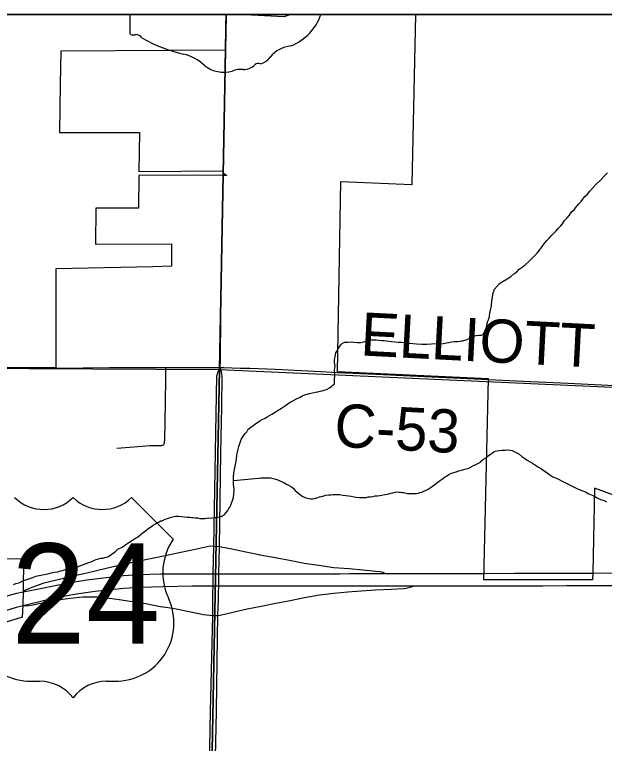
# Model space of a CAD drawing. Extents: x 0 to 34, y 0 to 22.
# Drawn here: x 6.216 to 6.991, y 19.941 to 20.9 of the extents above; entities that cross this region are included whole.
import ezdxf

# ---------------------------------------------------------------- set-up
doc = ezdxf.new("R2010")
doc.units = 0
for name, color, linetype in [('Default', 7, 'Continuous'), ('GM_X_City_Street', 7, 'Continuous'), ('GM_X_County_Road', 7, 'Continuous'), ('GM_X_County_Road_Text', 7, 'Continuous'), ('GM_X_Interchange_Ramps', 7, 'Continuous'), ('GM_X_Minor_River', 7, 'Continuous'), ('GM_X_Section', 7, 'Continuous'), ('GM_X_State_Route', 7, 'Continuous'), ('GM_X_Township_Road', 7, 'Continuous'), ('GM_X_Unincorporated_Text', 7, 'Continuous'), ('GM_X_US_Location', 7, 'Continuous'), ('GM_X_US_Route', 7, 'Continuous'), ('GM_X_US_Shield', 7, 'Continuous'), ('SH_Data', 7, 'Continuous')]:
    doc.layers.add(name, color=color, linetype=linetype)

msp = doc.modelspace()

# ---------------------------------------------------------------- linework, layer by layer
at = {"layer": 'Default'}
for points in [[(6.49402, 20.9), (5.49304, 20.9), (5.48293, 20.43816), (6.48534, 20.43303)], [(7.49088, 20.9), (6.49402, 20.9), (6.48534, 20.43303), (7.47924, 20.38842)]]:
    msp.add_lwpolyline(points, close=True, dxfattribs=at)
for points in [[(7.05728, 20.24803), (6.97837, 20.27716), (6.97611, 20.16577), (6.97572, 20.15654), (6.83292, 20.15618), (6.8388, 20.42065), (6.64029, 20.42983), (6.64454, 20.6803), (6.73852, 20.67644), (6.74355, 20.9), (6.5785, 20.9), (6.57014, 20.89705), (6.51038, 20.9), (6.49373, 20.9), (6.4929, 20.85332), (6.27639, 20.85193), (6.27568, 20.80908), (6.27458, 20.74489), (6.38016, 20.74486), (6.37927, 20.6937), (6.4902, 20.69438), (6.49015, 20.69161), (6.49485, 20.68811), (6.4901, 20.68847), (6.45677, 20.68866), (6.37919, 20.68816), (6.37847, 20.64553), (6.32271, 20.64518), (6.32199, 20.59781), (6.42221, 20.59822), (6.42195, 20.56879), (6.39789, 20.56827), (6.27007, 20.56534), (6.26978, 20.43556), (6.18963, 20.43507)], [(6.13367, 20.18377), (6.22753, 20.18449), (6.22689, 20.14091), (6.22664, 20.12302), (6.22582, 20.10729), (6.1749, 20.09133)]]:
    msp.add_lwpolyline(points, dxfattribs=at)
at = {"layer": 'GM_X_City_Street'}
for points in [[(6.41208, 20.33454), (6.41243, 20.33543), (6.41268, 20.33633), (6.41287, 20.33746), (6.41307, 20.33859), (6.41311, 20.33976), (6.41363, 20.3646), (6.41403, 20.3907), (6.41444, 20.4205), (6.41465, 20.43559)], [(6.35021, 20.32963), (6.35582, 20.33001), (6.3776, 20.3318), (6.39379, 20.33295), (6.40814, 20.33328), (6.40903, 20.33326), (6.40991, 20.33336), (6.4108, 20.3336), (6.41149, 20.33395), (6.41208, 20.33454)]]:
    msp.add_lwpolyline(points, dxfattribs=at)
at = {"layer": 'GM_X_County_Road'}
for points in [[(6.14024, 20.43373), (6.18986, 20.43451), (6.27002, 20.43501), (6.27101, 20.43502)], [(6.27101, 20.43502), (6.34054, 20.43578), (6.39955, 20.43561), (6.41465, 20.43559)], [(6.41465, 20.43559), (6.45455, 20.43556), (6.4862, 20.43568)], [(6.4862, 20.43568), (6.49126, 20.43554), (6.51238, 20.43497), (6.52488, 20.43471), (6.55848, 20.43347), (6.61851, 20.43033), (6.64052, 20.42928)], [(6.64052, 20.42928), (6.67097, 20.42784), (6.70995, 20.42613), (6.71737, 20.42577), (6.79271, 20.42206), (6.83903, 20.4201)], [(6.83903, 20.4201), (6.88486, 20.41771), (6.94386, 20.41488), (7.0395, 20.41007), (7.04664, 20.40978)]]:
    msp.add_lwpolyline(points, dxfattribs=at)
at = {"layer": 'GM_X_Interchange_Ramps'}
msp.add_line((6.47621, 20.10924), (6.48318, 20.10936), dxfattribs=at)
for points in [[(6.48502, 20.19975), (6.47767, 20.20037), (6.4727, 20.20055), (6.4534, 20.19639), (6.43432, 20.19244), (6.41611, 20.18849), (6.39681, 20.18432), (6.37729, 20.18059), (6.35887, 20.17643), (6.33606, 20.17116), (6.32365, 20.16801), (6.30903, 20.16467), (6.29463, 20.16174), (6.27646, 20.15715), (6.25437, 20.1518), (6.23842, 20.14629), (6.23453, 20.14466), (6.23116, 20.14305), (6.22713, 20.14036)], [(6.53752, 20.18914), (6.51986, 20.19288), (6.50121, 20.19661), (6.48748, 20.19921), (6.48502, 20.19975)], [(6.70321, 20.16452), (6.70119, 20.16542), (6.69858, 20.16637), (6.69562, 20.1669), (6.69079, 20.16747), (6.67347, 20.16894), (6.65582, 20.17096), (6.63566, 20.17226), (6.61526, 20.17533), (6.5964, 20.17796), (6.5771, 20.18169), (6.55824, 20.1852), (6.5385, 20.18893), (6.53752, 20.18914)], [(6.48318, 20.10936), (6.48602, 20.11002), (6.50256, 20.11393), (6.52168, 20.11806), (6.54005, 20.12181), (6.55917, 20.12556), (6.57829, 20.12931), (6.59703, 20.13305), (6.61653, 20.13643), (6.63565, 20.13868), (6.65373, 20.14045), (6.67169, 20.14191), (6.69027, 20.14337), (6.71094, 20.144), (6.72731, 20.14495), (6.73086, 20.14543), (6.73409, 20.14609), (6.73765, 20.14706), (6.74098, 20.14856)], [(6.22687, 20.12247), (6.23091, 20.12207), (6.23467, 20.12248), (6.24006, 20.12342), (6.24772, 20.12504), (6.2574, 20.12693), (6.27101, 20.12967), (6.28215, 20.13156), (6.29675, 20.13313), (6.30562, 20.13399), (6.31446, 20.13377), (6.32436, 20.13395), (6.33423, 20.13305), (6.35335, 20.13043), (6.36759, 20.12818), (6.38821, 20.12518), (6.40696, 20.12143), (6.41501, 20.12017)], [(6.41501, 20.12017), (6.42608, 20.11843), (6.4452, 20.11468), (6.46432, 20.11056), (6.47621, 20.10924)]]:
    msp.add_lwpolyline(points, dxfattribs=at)
at = {"layer": 'GM_X_Minor_River'}
for points in [[(6.83907, 20.49841), (6.8395, 20.5003), (6.84032, 20.50218), (6.84037, 20.50408), (6.84083, 20.50672), (6.8413, 20.50975), (6.84177, 20.51278), (6.84221, 20.51466), (6.84265, 20.51693), (6.84273, 20.51959), (6.84316, 20.52148), (6.84322, 20.52338), (6.84367, 20.52564), (6.84411, 20.52791), (6.8446, 20.5317), (6.84505, 20.53396), (6.84588, 20.53622), (6.84671, 20.53886), (6.85339, 20.54627), (6.85803, 20.54917), (6.86344, 20.55243), (6.86809, 20.55534), (6.87237, 20.55902), (6.87625, 20.56157), (6.87939, 20.5649), (6.88327, 20.56783), (6.88754, 20.57112), (6.89145, 20.57481), (6.89535, 20.5785), (6.89928, 20.58256), (6.9028, 20.58626), (6.90595, 20.58998), (6.90872, 20.5937), (6.9115, 20.59779), (6.91583, 20.60299), (6.91896, 20.60632), (6.9221, 20.60965), (6.92485, 20.61261), (6.92797, 20.61556), (6.93072, 20.61852), (6.93346, 20.62148), (6.93622, 20.62483), (6.939, 20.62893), (6.94215, 20.63263), (6.94528, 20.63597), (6.94807, 20.64045), (6.95157, 20.64301), (6.95354, 20.64561), (6.95553, 20.64859), (6.95827, 20.65155), (6.96063, 20.65415), (6.963, 20.65712), (6.96575, 20.66046), (6.96889, 20.66379), (6.97204, 20.6675), (6.97596, 20.67195), (6.98027, 20.67638), (6.98653, 20.68266), (6.99123, 20.68747), (6.99554, 20.6919)], [(6.53309, 20.36206), (6.53503, 20.36352), (6.53813, 20.36533), (6.54122, 20.36714), (6.54507, 20.36893), (6.54778, 20.37076), (6.55087, 20.37257), (6.55397, 20.37438), (6.5586, 20.37691), (6.56247, 20.37945), (6.56674, 20.38237), (6.57331, 20.38636), (6.57681, 20.3893), (6.58068, 20.39147), (6.58724, 20.39508), (6.59109, 20.39687), (6.59494, 20.39866), (6.59878, 20.40007), (6.60338, 20.40146), (6.60759, 20.40248), (6.61141, 20.40313), (6.61446, 20.4038), (6.61752, 20.40447), (6.6202, 20.40515), (6.62288, 20.40584), (6.62479, 20.40616), (6.62672, 20.40724), (6.62981, 20.40906), (6.63254, 20.41126), (6.63448, 20.41272), (6.63641, 20.41381), (6.63653, 20.41798), (6.63662, 20.42102), (6.6367, 20.42368), (6.63658, 20.43242), (6.63703, 20.43507), (6.63747, 20.43696), (6.6368, 20.44002), (6.63647, 20.44192), (6.63655, 20.44458), (6.63704, 20.44837), (6.6371, 20.45027), (6.63755, 20.45253), (6.63837, 20.45479), (6.63997, 20.45741), (6.6412, 20.46041), (6.6424, 20.46266), (6.64477, 20.46563), (6.64673, 20.46785), (6.6498, 20.4689), (6.65399, 20.46916), (6.65817, 20.46942), (6.66196, 20.46893), (6.6665, 20.46842), (6.67107, 20.46867), (6.67642, 20.47004), (6.68102, 20.47142), (6.68484, 20.47207), (6.6875, 20.472), (6.69129, 20.47189), (6.69471, 20.47179), (6.69811, 20.47131), (6.70153, 20.47121), (6.70455, 20.47075), (6.70796, 20.47027), (6.71136, 20.46979), (6.71592, 20.46966), (6.72046, 20.46915), (6.72501, 20.46902), (6.72994, 20.46849), (6.73523, 20.46758), (6.74432, 20.46694), (6.75114, 20.46636), (6.75761, 20.46656), (6.76407, 20.46675), (6.77928, 20.46745), (6.78348, 20.46809), (6.78692, 20.46875), (6.79036, 20.46941), (6.79378, 20.4697), (6.79873, 20.46993), (6.8014, 20.47024), (6.80331, 20.47056), (6.80522, 20.47088), (6.80789, 20.47157), (6.81019, 20.47226), (6.81327, 20.4737), (6.81599, 20.47552), (6.81945, 20.47694), (6.82289, 20.4776), (6.8267, 20.47825), (6.82974, 20.47816), (6.83205, 20.47923), (6.83325, 20.48148), (6.83408, 20.48374), (6.83489, 20.48561), (6.83612, 20.48862), (6.83658, 20.49126), (6.83703, 20.49353), (6.83787, 20.49655), (6.83907, 20.49841)], [(6.29738, 20.17352), (6.29928, 20.17384), (6.3016, 20.17492), (6.30965, 20.17773), (6.31349, 20.17913), (6.31656, 20.18019), (6.31887, 20.18126), (6.3208, 20.18234), (6.3231, 20.18304), (6.32618, 20.18409), (6.32923, 20.18476), (6.3319, 20.18507), (6.33458, 20.18575), (6.33687, 20.18606), (6.33918, 20.18714), (6.34228, 20.18933), (6.34461, 20.19116), (6.3481, 20.19334), (6.35161, 20.19666), (6.35739, 20.19953), (6.36205, 20.20282), (6.36592, 20.20537), (6.36941, 20.20755), (6.37212, 20.20937), (6.37483, 20.21119), (6.37715, 20.21264), (6.37947, 20.2141), (6.38259, 20.21667), (6.38492, 20.2185), (6.38802, 20.22069), (6.39114, 20.22326), (6.39463, 20.22582), (6.39813, 20.22838), (6.40122, 20.23019), (6.40354, 20.23165), (6.40546, 20.23235), (6.40778, 20.2338), (6.40969, 20.23413), (6.41355, 20.2363), (6.41699, 20.23696), (6.4193, 20.23803), (6.4216, 20.23873), (6.42352, 20.23943), (6.42543, 20.23976), (6.42771, 20.24007), (6.42999, 20.24), (6.43189, 20.23995), (6.4425, 20.23888), (6.44439, 20.23883), (6.44629, 20.23877), (6.44818, 20.23834), (6.45045, 20.23827), (6.4531, 20.23782), (6.45614, 20.23773), (6.45954, 20.23725), (6.46296, 20.23715), (6.46599, 20.23707), (6.46828, 20.23738), (6.47019, 20.23771), (6.47285, 20.23763), (6.47551, 20.23793), (6.47856, 20.23822), (6.48199, 20.23851), (6.48505, 20.23918), (6.48733, 20.23949), (6.48966, 20.24095), (6.49199, 20.24278), (6.49356, 20.24463), (6.49631, 20.24759), (6.49752, 20.25022), (6.49872, 20.25209), (6.49994, 20.25471), (6.50115, 20.25734), (6.50239, 20.26072), (6.50365, 20.26486), (6.50418, 20.26979), (6.50426, 20.27283), (6.50433, 20.2751), (6.50404, 20.27815), (6.50378, 20.28234), (6.50354, 20.28691), (6.50368, 20.29184), (6.50421, 20.29677), (6.50511, 20.30168), (6.50561, 20.30585), (6.50651, 20.31038), (6.5074, 20.31492), (6.50795, 20.3206), (6.50882, 20.32438), (6.50969, 20.32815), (6.51056, 20.33193), (6.51386, 20.34095), (6.51586, 20.34431), (6.51746, 20.34693), (6.51903, 20.34878), (6.52099, 20.35101), (6.523, 20.35475), (6.5265, 20.35731), (6.52883, 20.35914), (6.53115, 20.36059), (6.53309, 20.36206)], [(6.81939, 20.30669), (6.82247, 20.30812), (6.82594, 20.30992), (6.82826, 20.31137), (6.83022, 20.31322), (6.83255, 20.31505), (6.83526, 20.31687), (6.83838, 20.31944), (6.84148, 20.32163), (6.84419, 20.32345), (6.84612, 20.32454), (6.84805, 20.32562), (6.85034, 20.32594), (6.85302, 20.32662), (6.85683, 20.32689), (6.86101, 20.32715), (6.86482, 20.32742), (6.86746, 20.32696), (6.87011, 20.32651), (6.87872, 20.32208), (6.88279, 20.31854), (6.88651, 20.31577), (6.88987, 20.31378), (6.89361, 20.31177), (6.89697, 20.30977), (6.90069, 20.30701), (6.90479, 20.30461), (6.90852, 20.30222), (6.91225, 20.29983), (6.9156, 20.29745), (6.9197, 20.29468), (6.92342, 20.29191), (6.92831, 20.29025), (6.93166, 20.28825), (6.93503, 20.28663), (6.93839, 20.28464), (6.94214, 20.28301), (6.94626, 20.28099), (6.95075, 20.27858), (6.956, 20.27615), (6.96164, 20.27409), (6.96651, 20.27204), (6.971, 20.26963), (6.97738, 20.26679), (6.98186, 20.26438), (6.98635, 20.26197), (6.99087, 20.2607), (6.99424, 20.25908)], [(6.50354, 20.28691), (6.53668, 20.29013), (6.53935, 20.29044), (6.54164, 20.29075), (6.54429, 20.29067), (6.54619, 20.29062), (6.54885, 20.29054), (6.55226, 20.29045), (6.55566, 20.28959), (6.55905, 20.28873), (6.56281, 20.28748), (6.56618, 20.28586), (6.56993, 20.28423), (6.57329, 20.28224), (6.57665, 20.28024), (6.58003, 20.27862), (6.58188, 20.27705), (6.58482, 20.27392), (6.58705, 20.27196), (6.58965, 20.26999), (6.59187, 20.26802), (6.5941, 20.26644), (6.59859, 20.26403), (6.60274, 20.26315), (6.60502, 20.26308), (6.60768, 20.26301), (6.60996, 20.26332), (6.61187, 20.26364), (6.61456, 20.26471), (6.61686, 20.2654), (6.61916, 20.26609), (6.62222, 20.26677), (6.62491, 20.26783), (6.6291, 20.26809), (6.63176, 20.26839), (6.63443, 20.2687), (6.63709, 20.26862), (6.64013, 20.26853), (6.64354, 20.26843), (6.64732, 20.26794), (6.65111, 20.26745), (6.65489, 20.26697), (6.6583, 20.26649), (6.66207, 20.26562), (6.6651, 20.26515), (6.66926, 20.26465), (6.67229, 20.26456), (6.67495, 20.26449), (6.678, 20.26478), (6.68068, 20.26546), (6.68373, 20.26576), (6.68677, 20.26605), (6.68983, 20.26672), (6.69288, 20.26701), (6.69593, 20.26731), (6.69859, 20.26761), (6.7028, 20.26863), (6.70547, 20.26893), (6.70777, 20.26962), (6.71045, 20.27031), (6.71313, 20.27099), (6.71619, 20.27166), (6.71847, 20.27198), (6.72113, 20.2719), (6.72303, 20.27184), (6.72529, 20.2714), (6.72719, 20.27134), (6.73058, 20.27048), (6.73247, 20.27005), (6.74006, 20.26983), (6.74234, 20.26977), (6.74463, 20.27008), (6.74692, 20.27039), (6.74884, 20.2711), (6.75114, 20.27179), (6.75382, 20.27286), (6.75691, 20.27429), (6.75961, 20.27573), (6.76232, 20.27755), (6.76542, 20.27974), (6.76815, 20.28194), (6.77086, 20.28377), (6.7759, 20.28742), (6.77824, 20.28925), (6.78096, 20.29145), (6.78366, 20.2929), (6.78676, 20.29509), (6.79022, 20.29651), (6.79329, 20.29756), (6.79636, 20.29861), (6.79981, 20.29965), (6.80326, 20.30069), (6.80632, 20.30137), (6.80939, 20.30242), (6.81284, 20.30346), (6.81592, 20.30489), (6.81939, 20.30669)], [(6.21426, 20.15007), (6.21734, 20.1515), (6.22117, 20.15253), (6.22463, 20.15395), (6.22809, 20.15537), (6.23193, 20.15678), (6.23577, 20.15819), (6.23961, 20.1596), (6.24383, 20.161), (6.24804, 20.16202), (6.25454, 20.16335), (6.2595, 20.16435), (6.2641, 20.16574), (6.2683, 20.16638), (6.2725, 20.16702), (6.27594, 20.16806), (6.27862, 20.16874), (6.2813, 20.16942), (6.28399, 20.17048), (6.28705, 20.17116), (6.29087, 20.17181), (6.29393, 20.17248), (6.29738, 20.17352)]]:
    msp.add_lwpolyline(points, dxfattribs=at)
at = {"layer": 'GM_X_Section'}
for points in [[(5.48293, 20.43816), (6.48534, 20.43303), (6.46596, 19.43025), (5.4561, 19.43741)], [(6.48534, 20.43303), (7.47924, 20.38842), (7.45332, 19.38122), (6.71521, 19.42448), (6.46596, 19.43025)]]:
    msp.add_lwpolyline(points, close=True, dxfattribs=at)
at = {"layer": 'GM_X_State_Route'}
for p, q in [((6.49038, 20.69087), (6.49043, 20.69383)), ((6.49033, 20.68792), (6.49038, 20.69087)), ((6.48716, 20.52928), (6.48854, 20.59856)), ((6.48711, 20.3235), (6.48814, 20.38387)), ((6.48502, 20.19975), (6.48711, 20.3235)), ((6.48105, 19.98448), (6.48269, 20.08038))]:
    msp.add_line(p, q, dxfattribs=at)
for points in [[(6.49313, 20.85277), (6.49367, 20.88347), (6.49397, 20.9)], [(6.49043, 20.69383), (6.49098, 20.72527), (6.4912, 20.73518), (6.49191, 20.7739), (6.49226, 20.79621), (6.49245, 20.80883), (6.49268, 20.82423), (6.49282, 20.83361), (6.49313, 20.85277)], [(6.48854, 20.59856), (6.48921, 20.62457), (6.48959, 20.64861), (6.49033, 20.68792)], [(6.4862, 20.43568), (6.48635, 20.44581), (6.48675, 20.50425), (6.48716, 20.52928)], [(6.47767, 20.20037), (6.48179, 20.42447), (6.48327, 20.4306), (6.4862, 20.43568)], [(6.48814, 20.38387), (6.48882, 20.42411), (6.48783, 20.42949), (6.4862, 20.43568)], [(6.46479, 19.52084), (6.46612, 19.59885), (6.46901, 19.74424), (6.47355, 19.98326), (6.47621, 20.10924), (6.47654, 20.13859), (6.4767, 20.14839), (6.47702, 20.16435), (6.47767, 20.20037)], [(6.48369, 20.13084), (6.48388, 20.13866), (6.4841, 20.14841), (6.48436, 20.16443), (6.48502, 20.19975)], [(6.48269, 20.08038), (6.48318, 20.10936), (6.48369, 20.13084)], [(6.47935, 19.9038), (6.4806, 19.96287), (6.48103, 19.98348), (6.48105, 19.98448)]]:
    msp.add_lwpolyline(points, dxfattribs=at)
at = {"layer": 'GM_X_Township_Road'}
msp.add_lwpolyline([(7.49369, 20.9), (2.1, 20.9)], dxfattribs=at)
at = {"layer": 'GM_X_Unincorporated_Text'}
msp.add_lwpolyline([(6.61861, 20.9), (6.3673, 20.9), (6.3673, 20.87674)], dxfattribs=at)
for centre, radius, start, end in [((6.55271, 20.92343), 0.06994, 292.30889, 340.42752), ((6.37035, 20.87628), 0.00308, 171.49107, 258.30654), ((6.37082, 20.89675), 0.02352, 267.33899, 280.60386), ((6.37563, 20.86517), 0.00848, 29.74838, 93.27175), ((6.48269, 21.04497), 0.20192, 240.41292, 257.1985), ((6.5822, 20.82054), 0.0383, 94.40312, 142.57675), ((6.42249, 20.78681), 0.06318, 47.18415, 75.83597), ((6.53367, 20.85732), 0.0226, 282.87319, 323.27711), ((6.49082, 20.86418), 0.04009, 230.70037, 286.29183), ((6.51398, 20.79499), 0.03294, 85.6951, 111.20996), ((6.51691, 20.84919), 0.02136, 268.77705, 315.54927), ((6.53623, 20.82981), 0.00601, 65.75173, 132.64842)]:
    msp.add_arc(centre, radius, start, end, dxfattribs=at)
at = {"layer": 'GM_X_US_Route'}
for points in [[(6.83346, 20.1649), (6.87362, 20.16499), (6.88647, 20.16504)], [(6.88647, 20.16504), (6.92404, 20.1652), (6.97635, 20.16521)], [(6.97635, 20.16521), (7.47754, 20.16625)], [(6.22713, 20.14036), (6.24542, 20.14427), (6.26925, 20.14908), (6.29182, 20.15336), (6.31083, 20.15635), (6.3361, 20.15952), (6.35896, 20.16184), (6.3794, 20.16319), (6.40796, 20.16414), (6.44648, 20.16441), (6.46761, 20.16424), (6.47702, 20.16435), (6.48436, 20.16443), (6.49685, 20.16415), (6.53603, 20.16425), (6.59632, 20.16427), (6.64359, 20.16441), (6.65663, 20.16447), (6.67031, 20.16454), (6.70321, 20.16452), (6.72937, 20.1645), (6.78658, 20.16483), (6.83346, 20.1649)], [(6.22687, 20.12247), (6.25742, 20.13), (6.2775, 20.13436), (6.29712, 20.13785), (6.32176, 20.14143), (6.34217, 20.14378), (6.35953, 20.14533), (6.38065, 20.14664), (6.41112, 20.14764), (6.44905, 20.14832), (6.4767, 20.14839), (6.47776, 20.1484)], [(6.47776, 20.1484), (6.4841, 20.14841), (6.49072, 20.14843), (6.53547, 20.14841), (6.5877, 20.14848), (6.62936, 20.14844), (6.66976, 20.14843), (6.69961, 20.14853), (6.74098, 20.14856), (6.78478, 20.14859), (6.79659, 20.1486), (6.82457, 20.14857), (6.83244, 20.14857)], [(6.83244, 20.14857), (6.91036, 20.14861), (6.94129, 20.1487)], [(6.94129, 20.1487), (6.95326, 20.14873), (6.97557, 20.14875)], [(6.97557, 20.14875), (6.97653, 20.14875), (6.99181, 20.14877), (7.02102, 20.14901), (7.07884, 20.14928), (7.11787, 20.14879), (7.18471, 20.14882), (7.29532, 20.1491), (7.44569, 20.14938), (7.46894, 20.14921), (7.47709, 20.14913)], [(5.86436, 19.9308), (5.9099, 19.96828), (5.94566, 19.99738), (5.96465, 20.01226), (5.98306, 20.02566), (5.99662, 20.03503), (6.01603, 20.04769), (6.03578, 20.0598), (6.04483, 20.06506), (6.05625, 20.07164), (6.06718, 20.07748), (6.07886, 20.08331), (6.09119, 20.08956), (6.10944, 20.09876), (6.13158, 20.10788), (6.14253, 20.11279), (6.15465, 20.11798), (6.16688, 20.12256), (6.18288, 20.12809), (6.19929, 20.13321), (6.20924, 20.13618), (6.21866, 20.1386), (6.22713, 20.14036)], [(5.89177, 19.93103), (5.90961, 19.94573), (5.95062, 19.97901), (5.97006, 19.99449), (5.98793, 20.00795), (6.00571, 20.02048), (6.02799, 20.03522), (6.04853, 20.04808), (6.05712, 20.05308), (6.06835, 20.05987), (6.08239, 20.06748), (6.10198, 20.07699), (6.12071, 20.08542), (6.14427, 20.09519), (6.16167, 20.10198), (6.18346, 20.10945), (6.20423, 20.11595), (6.2184, 20.12018), (6.22687, 20.12247)]]:
    msp.add_lwpolyline(points, dxfattribs=at)
at = {"layer": 'GM_X_US_Shield'}
for p, q in [((6.42447, 20.20969), (6.36954, 20.26462)), ((6.2377, 20.02292), (6.24869, 20.02292)), ((6.33658, 20.02292), (6.34757, 20.02292))]:
    msp.add_line(p, q, dxfattribs=at)
for centre, radius, start, end in [((6.25418, 20.30385), 0.05493, 225.573, 314.427), ((6.33109, 20.30385), 0.05493, 225.573, 314.427), ((6.48747, 20.16557), 0.0769, 144.99907, 205.45288), ((6.23685, 20.09982), 0.0769, 154.83192, 270.63826), ((6.34842, 20.09982), 0.0769, 269.36174, 25.16808), ((6.24869, 19.96799), 0.05493, 36.8699, 90), ((6.33658, 19.96799), 0.05493, 90, 143.1301)]:
    msp.add_arc(centre, radius, start, end, dxfattribs=at)
at = {"layer": 'SH_Data'}
msp.add_line((2.1, 20.9), (8.9, 20.9), dxfattribs=at)

# ---------------------------------------------------------------- texts
at = {"layer": 'GM_X_County_Road_Text'}
for s, rotation, p in [('ELLIOTT', 357.01641, (6.66978, 20.45167)), ('C-53', 356.93318, (6.63514, 20.3317))]:
    msp.add_text(s, height=0.056818, rotation=rotation, dxfattribs=at).set_placement(p)
at = {"layer": 'GM_X_US_Location'}
for s, p in [('0', (6.29256, 20.13724)), ('/', (6.29258, 20.13724))]:
    msp.add_text(s, height=0.000189, dxfattribs=at).set_placement(p)
msp.add_text('24', height=0.000189, rotation=0.00001, dxfattribs=at).set_placement((6.25347, 20.09803))
at = {"layer": 'GM_X_US_Shield'}
msp.add_text('24', height=0.131836, dxfattribs=at).set_placement((6.21129, 20.07236))

doc.saveas('drawing.dxf')
